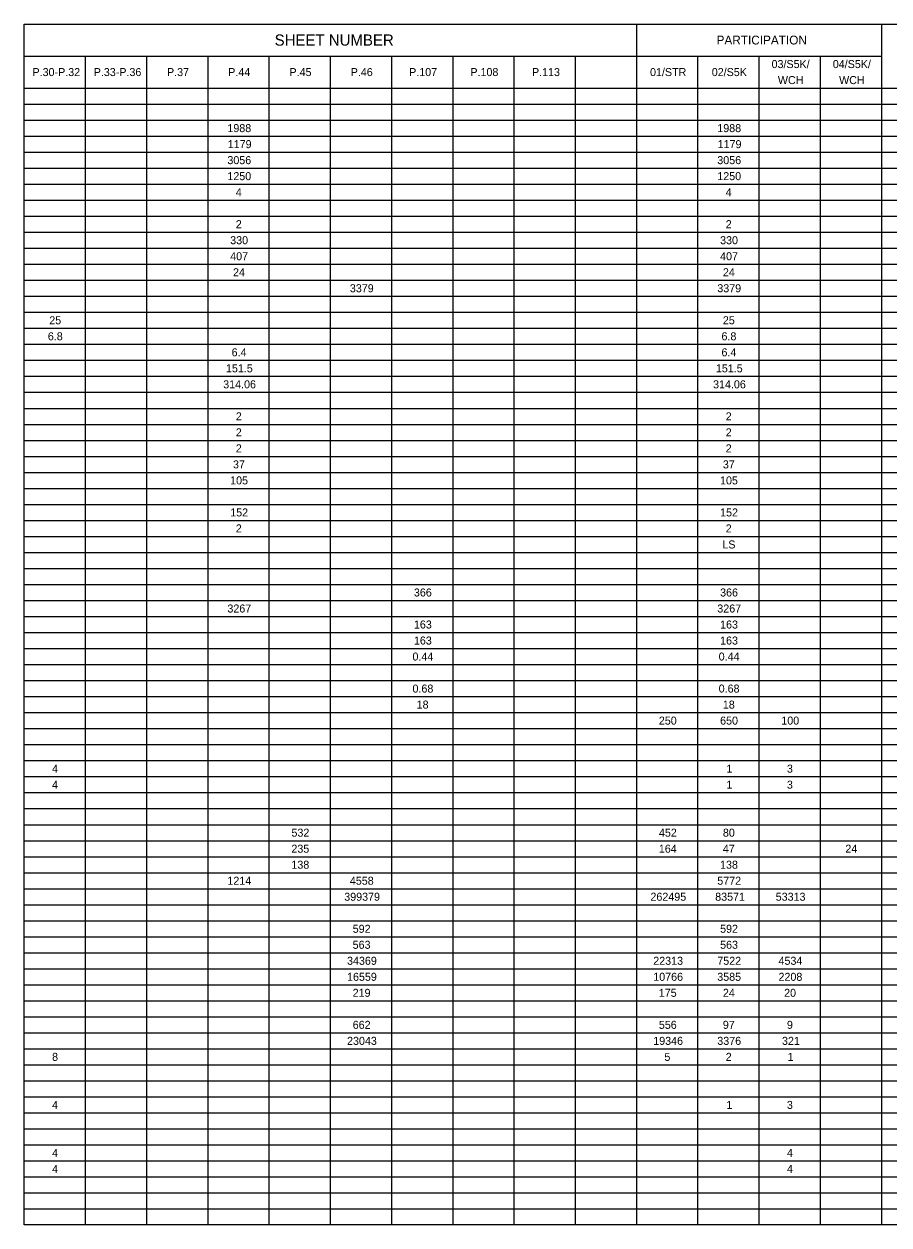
# Model space of a CAD drawing. Extents: x 12522 to 13018, y 1124 to 1902.
# Drawn here: x 12721.3 to 12736.42, y 1828.79 to 1849.79 of the extents above; entities that cross this region are included whole.
import ezdxf

# ---------------------------------------------------------------- set-up
doc = ezdxf.new("R2010")
doc.units = 0
for name, color, linetype in [('SC_Scratch1', 7, 'Continuous'), ('SH_Data', 7, 'Continuous'), ('SH_Text', 7, 'Continuous')]:
    doc.layers.add(name, color=color, linetype=linetype)

msp = doc.modelspace()

# ---------------------------------------------------------------- linework, layer by layer
at = {"layer": 'SC_Scratch1'}
msp.add_lwpolyline([(12721.301, 1849.791), (12751.801, 1849.791), (12751.801, 1828.791), (12721.301, 1828.791)], close=True, dxfattribs=at)
at = {"layer": 'SH_Data'}
for p, q in [((12732.006, 1849.791), (12732.006, 1828.791)), ((12736.289, 1849.791), (12736.289, 1828.791)), ((12721.301, 1849.231), (12736.289, 1849.231)), ((12722.371, 1849.231), (12722.371, 1828.791)), ((12723.442, 1849.231), (12723.442, 1828.791)), ((12724.512, 1849.231), (12724.512, 1828.791)), ((12725.583, 1849.231), (12725.583, 1828.791)), ((12726.654, 1849.231), (12726.654, 1828.791)), ((12727.724, 1849.231), (12727.724, 1828.791)), ((12728.795, 1849.231), (12728.795, 1828.791)), ((12729.865, 1849.231), (12729.865, 1828.791)), ((12730.936, 1849.231), (12730.936, 1828.791)), ((12733.077, 1849.231), (12733.077, 1828.791)), ((12734.148, 1849.231), (12734.148, 1828.791)), ((12735.218, 1849.231), (12735.218, 1828.791)), ((12721.301, 1848.671), (12751.804, 1848.671)), ((12721.301, 1848.391), (12751.804, 1848.391)), ((12721.301, 1848.111), (12751.804, 1848.111)), ((12721.301, 1847.831), (12751.804, 1847.831)), ((12721.301, 1847.551), (12751.804, 1847.551)), ((12721.301, 1847.271), (12751.804, 1847.271)), ((12721.301, 1846.991), (12751.804, 1846.991)), ((12721.301, 1846.711), (12751.804, 1846.711)), ((12721.301, 1846.431), (12751.804, 1846.431)), ((12721.301, 1846.151), (12751.804, 1846.151)), ((12721.301, 1845.871), (12751.804, 1845.871)), ((12721.301, 1845.591), (12751.804, 1845.591)), ((12721.301, 1845.311), (12751.804, 1845.311)), ((12721.301, 1845.031), (12751.804, 1845.031)), ((12721.301, 1844.751), (12751.804, 1844.751)), ((12721.301, 1844.471), (12751.804, 1844.471)), ((12721.301, 1844.191), (12751.804, 1844.191)), ((12721.301, 1843.911), (12751.804, 1843.911)), ((12721.301, 1843.631), (12751.804, 1843.631)), ((12721.301, 1843.351), (12751.804, 1843.351)), ((12721.301, 1843.071), (12751.804, 1843.071)), ((12721.301, 1842.791), (12751.804, 1842.791)), ((12721.301, 1842.511), (12751.804, 1842.511)), ((12721.301, 1842.231), (12751.804, 1842.231)), ((12721.301, 1841.951), (12751.804, 1841.951)), ((12721.301, 1841.671), (12751.804, 1841.671)), ((12721.301, 1841.391), (12751.804, 1841.391)), ((12721.301, 1841.111), (12751.804, 1841.111)), ((12721.301, 1840.831), (12751.804, 1840.831)), ((12721.301, 1840.551), (12751.804, 1840.551)), ((12721.301, 1840.271), (12751.804, 1840.271)), ((12721.301, 1839.991), (12751.804, 1839.991)), ((12721.301, 1839.711), (12751.804, 1839.711)), ((12721.301, 1839.431), (12751.804, 1839.431)), ((12721.301, 1839.151), (12751.804, 1839.151)), ((12721.301, 1838.871), (12751.804, 1838.871)), ((12721.301, 1838.591), (12751.804, 1838.591)), ((12721.301, 1838.311), (12751.804, 1838.311)), ((12721.301, 1838.031), (12751.804, 1838.031)), ((12721.301, 1837.751), (12751.804, 1837.751)), ((12721.301, 1837.471), (12751.804, 1837.471)), ((12721.301, 1837.191), (12751.804, 1837.191)), ((12721.301, 1836.911), (12751.804, 1836.911)), ((12721.301, 1836.631), (12751.804, 1836.631)), ((12721.301, 1836.351), (12751.804, 1836.351)), ((12721.301, 1836.071), (12751.804, 1836.071)), ((12721.301, 1835.791), (12751.804, 1835.791)), ((12721.301, 1835.511), (12751.804, 1835.511)), ((12721.301, 1835.231), (12751.804, 1835.231)), ((12721.301, 1834.951), (12751.804, 1834.951)), ((12721.301, 1834.671), (12751.804, 1834.671)), ((12721.301, 1834.391), (12751.804, 1834.391)), ((12721.301, 1834.111), (12751.804, 1834.111)), ((12721.301, 1833.831), (12751.804, 1833.831)), ((12721.301, 1833.551), (12751.804, 1833.551)), ((12721.301, 1833.271), (12751.804, 1833.271)), ((12721.301, 1832.991), (12751.804, 1832.991)), ((12721.301, 1832.711), (12751.804, 1832.711)), ((12721.301, 1832.431), (12751.804, 1832.431)), ((12721.301, 1832.151), (12751.804, 1832.151)), ((12721.301, 1831.871), (12751.804, 1831.871)), ((12721.301, 1831.591), (12751.804, 1831.591)), ((12721.301, 1831.311), (12751.804, 1831.311)), ((12721.301, 1831.031), (12751.804, 1831.031)), ((12721.301, 1830.751), (12751.804, 1830.751)), ((12721.301, 1830.471), (12751.804, 1830.471)), ((12721.301, 1830.191), (12751.804, 1830.191)), ((12721.301, 1829.911), (12751.804, 1829.911)), ((12721.301, 1829.631), (12751.804, 1829.631)), ((12721.301, 1829.351), (12751.804, 1829.351)), ((12721.301, 1829.071), (12751.804, 1829.071))]:
    msp.add_line(p, q, dxfattribs=at)

# ---------------------------------------------------------------- texts
at = {"layer": 'SH_Text'}
for s, height, p in [('SHEET NUMBER', 0.196, (12725.682, 1849.413)), ('PARTICIPATION', 0.154, (12733.408, 1849.434)), ('03/S5K/', 0.14, (12734.37, 1849.021)), ('04/S5K/', 0.14, (12735.44, 1849.021)), ('P.30-P.32', 0.14, (12721.449, 1848.881)), ('P.33-P.36', 0.14, (12722.519, 1848.881)), ('P.37', 0.14, (12723.8, 1848.881)), ('P.44', 0.14, (12724.871, 1848.881)), ('P.45', 0.14, (12725.941, 1848.881)), ('P.46', 0.14, (12727.012, 1848.881)), ('P.107', 0.14, (12728.033, 1848.881)), ('P.108', 0.14, (12729.104, 1848.881)), ('P.113', 0.14, (12730.181, 1848.881)), ('01/STR', 0.14, (12732.245, 1848.881)), ('02/S5K', 0.14, (12733.324, 1848.881)), ('WCH', 0.14, (12734.48, 1848.741)), ('WCH', 0.14, (12735.55, 1848.741)), ('1988', 0.14, (12724.856, 1847.901)), ('1988', 0.14, (12733.421, 1847.901)), ('1179', 0.14, (12724.862, 1847.621)), ('1179', 0.14, (12733.427, 1847.621)), ('3056', 0.14, (12724.856, 1847.341)), ('3056', 0.14, (12733.421, 1847.341)), ('1250', 0.14, (12724.856, 1847.061)), ('1250', 0.14, (12733.421, 1847.061)), ('4', 0.14, (12725.003, 1846.781)), ('4', 0.14, (12733.568, 1846.781)), ('2', 0.14, (12725.003, 1846.221)), ('2', 0.14, (12733.568, 1846.221)), ('330', 0.14, (12724.905, 1845.941)), ('330', 0.14, (12733.47, 1845.941)), ('407', 0.14, (12724.905, 1845.661)), ('407', 0.14, (12733.47, 1845.661)), ('24', 0.14, (12724.954, 1845.381)), ('24', 0.14, (12733.519, 1845.381)), ('3379', 0.14, (12726.997, 1845.101)), ('3379', 0.14, (12733.421, 1845.101)), ('25', 0.14, (12721.742, 1844.541)), ('25', 0.14, (12733.518, 1844.541)), ('6.8', 0.14, (12721.717, 1844.261)), ('6.8', 0.14, (12733.494, 1844.261)), ('6.4', 0.14, (12724.93, 1843.981)), ('6.4', 0.14, (12733.494, 1843.981)), ('151.5', 0.14, (12724.831, 1843.701)), ('151.5', 0.14, (12733.396, 1843.701)), ('314.06', 0.14, (12724.783, 1843.421)), ('314.06', 0.14, (12733.347, 1843.421)), ('2', 0.14, (12725.003, 1842.861)), ('2', 0.14, (12733.568, 1842.861)), ('2', 0.14, (12725.003, 1842.581)), ('2', 0.14, (12733.568, 1842.581)), ('2', 0.14, (12725.003, 1842.301)), ('2', 0.14, (12733.568, 1842.301)), ('37', 0.14, (12724.954, 1842.021)), ('37', 0.14, (12733.518, 1842.021)), ('105', 0.14, (12724.904, 1841.741)), ('105', 0.14, (12733.469, 1841.741)), ('152', 0.14, (12724.906, 1841.181)), ('152', 0.14, (12733.47, 1841.181)), ('2', 0.14, (12725.003, 1840.901)), ('2', 0.14, (12733.568, 1840.901)), ('LS', 0.14, (12733.509, 1840.621)), ('366', 0.14, (12728.117, 1839.781)), ('366', 0.14, (12733.47, 1839.781)), ('3267', 0.14, (12724.856, 1839.501)), ('3267', 0.14, (12733.421, 1839.501)), ('163', 0.14, (12728.117, 1839.221)), ('163', 0.14, (12733.47, 1839.221)), ('163', 0.14, (12728.117, 1838.941)), ('163', 0.14, (12733.47, 1838.941)), ('0.44', 0.14, (12728.092, 1838.661)), ('0.44', 0.14, (12733.445, 1838.661)), ('0.68', 0.14, (12728.092, 1838.101)), ('0.68', 0.14, (12733.445, 1838.101)), ('18', 0.14, (12728.165, 1837.821)), ('18', 0.14, (12733.518, 1837.821)), ('250', 0.14, (12732.399, 1837.541)), ('650', 0.14, (12733.47, 1837.541)), ('100', 0.14, (12734.54, 1837.541)), ('4', 0.14, (12721.791, 1836.701)), ('1', 0.14, (12733.58, 1836.701)), ('3', 0.14, (12734.638, 1836.701)), ('4', 0.14, (12721.791, 1836.421)), ('1', 0.14, (12733.58, 1836.421)), ('3', 0.14, (12734.638, 1836.421)), ('532', 0.14, (12725.976, 1835.581)), ('452', 0.14, (12732.4, 1835.581)), ('80', 0.14, (12733.519, 1835.581)), ('235', 0.14, (12725.975, 1835.301)), ('164', 0.14, (12732.399, 1835.301)), ('47', 0.14, (12733.518, 1835.301)), ('24', 0.14, (12735.66, 1835.301)), ('138', 0.14, (12725.975, 1835.021)), ('138', 0.14, (12733.469, 1835.021)), ('1214', 0.14, (12724.856, 1834.741)), ('4558', 0.14, (12726.997, 1834.741)), ('5772', 0.14, (12733.421, 1834.741)), ('399379', 0.14, (12726.899, 1834.461)), ('262495', 0.14, (12732.252, 1834.461)), ('83571', 0.14, (12733.384, 1834.461)), ('53313', 0.14, (12734.442, 1834.461)), ('592', 0.14, (12727.047, 1833.901)), ('592', 0.14, (12733.47, 1833.901)), ('563', 0.14, (12727.046, 1833.621)), ('563', 0.14, (12733.47, 1833.621)), ('34369', 0.14, (12726.948, 1833.341)), ('22313', 0.14, (12732.301, 1833.341)), ('7522', 0.14, (12733.421, 1833.341)), ('4534', 0.14, (12734.491, 1833.341)), ('16559', 0.14, (12726.948, 1833.061)), ('10766', 0.14, (12732.301, 1833.061)), ('3585', 0.14, (12733.42, 1833.061)), ('2208', 0.14, (12734.491, 1833.061)), ('219', 0.14, (12727.046, 1832.781)), ('175', 0.14, (12732.398, 1832.781)), ('24', 0.14, (12733.519, 1832.781)), ('20', 0.14, (12734.589, 1832.781)), ('662', 0.14, (12727.047, 1832.221)), ('556', 0.14, (12732.399, 1832.221)), ('97', 0.14, (12733.518, 1832.221)), ('9', 0.14, (12734.638, 1832.221)), ('23043', 0.14, (12726.948, 1831.941)), ('19346', 0.14, (12732.301, 1831.941)), ('3376', 0.14, (12733.421, 1831.941)), ('321', 0.14, (12734.552, 1831.941)), ('8', 0.14, (12721.791, 1831.661)), ('5', 0.14, (12732.496, 1831.661)), ('2', 0.14, (12733.568, 1831.661)), ('1', 0.14, (12734.65, 1831.661)), ('4', 0.14, (12721.791, 1830.821)), ('1', 0.14, (12733.58, 1830.821)), ('3', 0.14, (12734.638, 1830.821)), ('4', 0.14, (12721.791, 1829.981)), ('4', 0.14, (12734.638, 1829.981)), ('4', 0.14, (12721.791, 1829.701)), ('4', 0.14, (12734.638, 1829.701))]:
    msp.add_text(s, height=height, dxfattribs=at).set_placement(p)

doc.saveas('drawing.dxf')
